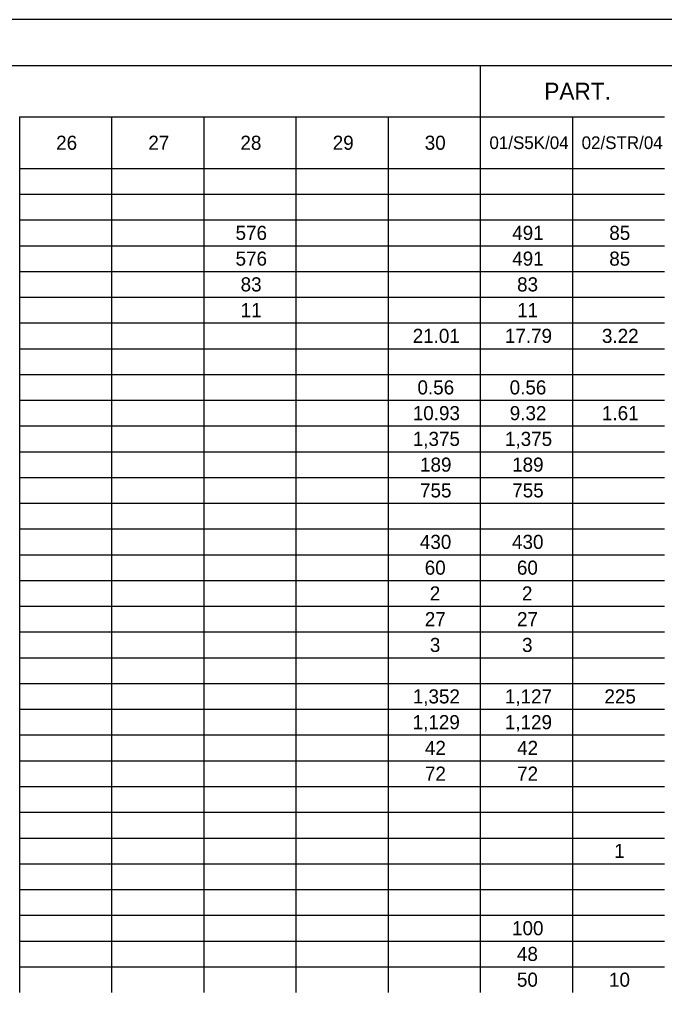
# Model space of a CAD drawing. Extents: x 0 to 34, y 0 to 22.
# Drawn here: x 8.52 to 15.54, y 11.42 to 22 of the extents above; entities that cross this region are included whole.
import ezdxf

# ---------------------------------------------------------------- set-up
doc = ezdxf.new("R2010")
doc.units = 0
for name, color, linetype in [('SH_Border', 7, 'Continuous'), ('SH_Cut_Line', 7, 'Continuous'), ('SH_Text', 7, 'Continuous')]:
    doc.layers.add(name, color=color, linetype=linetype)

msp = doc.modelspace()

# ---------------------------------------------------------------- linework, layer by layer
at = {"layer": 'SH_Border'}
msp.add_lwpolyline([(1.5, 21.5), (33.5, 21.5), (33.5, 0.5), (1.5, 0.5)], close=True, dxfattribs=at)
at = {"layer": 'SH_Cut_Line'}
msp.add_lwpolyline([(0, 0), (34, 0), (34, 22), (0, 22)], close=True, dxfattribs=at)
at = {"layer": 'SH_Text'}
for p, q in [((8.519, 21.5), (9.521, 21.5)), ((9.521, 21.5), (11.527, 21.5)), ((11.527, 21.5), (12.529, 21.5)), ((12.529, 21.5), (13.532, 21.5)), ((13.532, 21.5), (14.535, 21.5)), ((13.532, 21.5), (13.532, 21.22)), ((14.535, 21.5), (15.537, 21.5)), ((13.532, 21.22), (13.532, 20.94)), ((8.519, 20.94), (9.521, 20.94)), ((8.519, 20.94), (8.519, 20.66)), ((9.521, 20.94), (11.527, 20.94)), ((9.521, 20.94), (9.521, 20.66)), ((10.524, 20.94), (10.524, 20.66)), ((11.527, 20.94), (12.529, 20.94)), ((11.527, 20.94), (11.527, 20.66)), ((12.529, 20.94), (13.532, 20.94)), ((12.529, 20.94), (12.529, 20.66)), ((13.532, 20.94), (14.535, 20.94)), ((13.532, 20.94), (13.532, 20.66)), ((14.535, 20.94), (15.537, 20.94)), ((14.535, 20.94), (14.535, 20.66)), ((8.519, 20.66), (8.519, 20.38)), ((9.521, 20.66), (9.521, 20.38)), ((10.524, 20.66), (10.524, 20.38)), ((11.527, 20.66), (11.527, 20.38)), ((12.529, 20.66), (12.529, 20.38)), ((13.532, 20.66), (13.532, 20.38)), ((14.535, 20.66), (14.535, 20.38)), ((8.519, 20.38), (9.521, 20.38)), ((8.519, 20.38), (8.519, 20.1)), ((9.521, 20.38), (11.527, 20.38)), ((9.521, 20.38), (9.521, 20.1)), ((10.524, 20.38), (10.524, 20.1)), ((11.527, 20.38), (12.529, 20.38)), ((11.527, 20.38), (11.527, 20.1)), ((12.529, 20.38), (13.532, 20.38)), ((12.529, 20.38), (12.529, 20.1)), ((13.532, 20.38), (14.535, 20.38)), ((13.532, 20.38), (13.532, 20.1)), ((14.535, 20.38), (15.537, 20.38)), ((14.535, 20.38), (14.535, 20.1)), ((8.519, 20.1), (9.521, 20.1)), ((8.519, 20.1), (8.519, 18.7)), ((9.521, 20.1), (11.527, 20.1)), ((9.521, 20.1), (9.521, 18.7)), ((10.524, 20.1), (10.524, 18.7)), ((11.527, 20.1), (12.529, 20.1)), ((11.527, 20.1), (11.527, 18.7)), ((12.529, 20.1), (13.532, 20.1)), ((12.529, 20.1), (12.529, 18.7)), ((13.532, 20.1), (14.535, 20.1)), ((13.532, 20.1), (13.532, 18.7)), ((14.535, 20.1), (15.537, 20.1)), ((14.535, 20.1), (14.535, 18.7)), ((8.519, 19.82), (9.521, 19.82)), ((9.521, 19.82), (11.527, 19.82)), ((11.527, 19.82), (12.529, 19.82)), ((12.529, 19.82), (13.532, 19.82)), ((13.532, 19.82), (14.535, 19.82)), ((14.535, 19.82), (15.537, 19.82)), ((8.519, 19.54), (9.521, 19.54)), ((9.521, 19.54), (11.527, 19.54)), ((11.527, 19.54), (12.529, 19.54)), ((12.529, 19.54), (13.532, 19.54)), ((13.532, 19.54), (14.535, 19.54)), ((14.535, 19.54), (15.537, 19.54)), ((8.519, 19.26), (9.521, 19.26)), ((9.521, 19.26), (11.527, 19.26)), ((11.527, 19.26), (12.529, 19.26)), ((12.529, 19.26), (13.532, 19.26)), ((13.532, 19.26), (14.535, 19.26)), ((14.535, 19.26), (15.537, 19.26)), ((8.519, 18.98), (9.521, 18.98)), ((9.521, 18.98), (11.527, 18.98)), ((11.527, 18.98), (12.529, 18.98)), ((12.529, 18.98), (13.532, 18.98)), ((13.532, 18.98), (14.535, 18.98)), ((14.535, 18.98), (15.537, 18.98)), ((8.519, 18.7), (9.521, 18.7)), ((8.519, 18.7), (8.519, 18.14)), ((9.521, 18.7), (11.527, 18.7)), ((9.521, 18.7), (9.521, 18.14)), ((10.524, 18.7), (10.524, 18.14)), ((11.527, 18.7), (12.529, 18.7)), ((11.527, 18.7), (11.527, 18.14)), ((12.529, 18.7), (13.532, 18.7)), ((12.529, 18.7), (12.529, 18.14)), ((13.532, 18.7), (14.535, 18.7)), ((13.532, 18.7), (13.532, 18.14)), ((14.535, 18.7), (15.537, 18.7)), ((14.535, 18.7), (14.535, 18.14)), ((8.519, 18.42), (9.521, 18.42)), ((9.521, 18.42), (11.527, 18.42)), ((11.527, 18.42), (12.529, 18.42)), ((12.529, 18.42), (13.532, 18.42)), ((13.532, 18.42), (14.535, 18.42)), ((14.535, 18.42), (15.537, 18.42)), ((8.519, 18.14), (9.521, 18.14)), ((8.519, 18.14), (8.519, 17.86)), ((9.521, 18.14), (11.527, 18.14)), ((9.521, 18.14), (9.521, 17.86)), ((10.524, 18.14), (10.524, 17.86)), ((11.527, 18.14), (12.529, 18.14)), ((11.527, 18.14), (11.527, 17.86)), ((12.529, 18.14), (13.532, 18.14)), ((12.529, 18.14), (12.529, 17.86)), ((13.532, 18.14), (14.535, 18.14)), ((13.532, 18.14), (13.532, 17.86)), ((14.535, 18.14), (15.537, 18.14)), ((14.535, 18.14), (14.535, 17.86)), ((8.519, 17.86), (9.521, 17.86)), ((8.519, 17.86), (8.519, 17.58)), ((9.521, 17.86), (11.527, 17.86)), ((9.521, 17.86), (9.521, 17.58)), ((10.524, 17.86), (10.524, 17.58)), ((11.527, 17.86), (12.529, 17.86)), ((11.527, 17.86), (11.527, 17.58)), ((12.529, 17.86), (13.532, 17.86)), ((12.529, 17.86), (12.529, 17.58)), ((13.532, 17.86), (14.535, 17.86)), ((13.532, 17.86), (13.532, 17.58)), ((14.535, 17.86), (15.537, 17.86)), ((14.535, 17.86), (14.535, 17.58)), ((8.519, 17.58), (9.521, 17.58)), ((8.519, 17.58), (8.519, 17.3)), ((9.521, 17.58), (11.527, 17.58)), ((9.521, 17.58), (9.521, 17.3)), ((10.524, 17.58), (10.524, 17.3)), ((11.527, 17.58), (12.529, 17.58)), ((11.527, 17.58), (11.527, 17.3)), ((12.529, 17.58), (13.532, 17.58)), ((12.529, 17.58), (12.529, 17.3)), ((13.532, 17.58), (14.535, 17.58)), ((13.532, 17.58), (13.532, 17.3)), ((14.535, 17.58), (15.537, 17.58)), ((14.535, 17.58), (14.535, 17.3)), ((8.519, 17.3), (9.521, 17.3)), ((8.519, 17.3), (8.519, 17.02)), ((9.521, 17.3), (11.527, 17.3)), ((9.521, 17.3), (9.521, 17.02)), ((10.524, 17.3), (10.524, 17.02)), ((11.527, 17.3), (12.529, 17.3)), ((11.527, 17.3), (11.527, 17.02)), ((12.529, 17.3), (13.532, 17.3)), ((12.529, 17.3), (12.529, 17.02)), ((13.532, 17.3), (14.535, 17.3)), ((13.532, 17.3), (13.532, 17.02)), ((14.535, 17.3), (15.537, 17.3)), ((14.535, 17.3), (14.535, 17.02)), ((8.519, 17.02), (9.521, 17.02)), ((8.519, 17.02), (8.519, 16.74)), ((9.521, 17.02), (11.527, 17.02)), ((9.521, 17.02), (9.521, 16.74)), ((10.524, 17.02), (10.524, 16.74)), ((11.527, 17.02), (12.529, 17.02)), ((11.527, 17.02), (11.527, 16.74)), ((12.529, 17.02), (13.532, 17.02)), ((12.529, 17.02), (12.529, 16.74)), ((13.532, 17.02), (14.535, 17.02)), ((13.532, 17.02), (13.532, 16.74)), ((14.535, 17.02), (15.537, 17.02)), ((14.535, 17.02), (14.535, 16.74)), ((8.519, 16.74), (9.521, 16.74)), ((8.519, 16.74), (8.519, 16.18)), ((9.521, 16.74), (11.527, 16.74)), ((9.521, 16.74), (9.521, 16.18)), ((10.524, 16.74), (10.524, 16.18)), ((11.527, 16.74), (12.529, 16.74)), ((11.527, 16.74), (11.527, 16.18)), ((12.529, 16.74), (13.532, 16.74)), ((12.529, 16.74), (12.529, 16.18)), ((13.532, 16.74), (14.535, 16.74)), ((13.532, 16.74), (13.532, 16.18)), ((14.535, 16.74), (15.537, 16.74)), ((14.535, 16.74), (14.535, 16.18)), ((8.519, 16.46), (9.521, 16.46)), ((9.521, 16.46), (11.527, 16.46)), ((11.527, 16.46), (12.529, 16.46)), ((12.529, 16.46), (13.532, 16.46)), ((13.532, 16.46), (14.535, 16.46)), ((14.535, 16.46), (15.537, 16.46)), ((8.519, 16.18), (9.521, 16.18)), ((8.519, 16.18), (8.519, 15.9)), ((9.521, 16.18), (11.527, 16.18)), ((9.521, 16.18), (9.521, 15.9)), ((10.524, 16.18), (10.524, 15.9)), ((11.527, 16.18), (12.529, 16.18)), ((11.527, 16.18), (11.527, 15.9)), ((12.529, 16.18), (13.532, 16.18)), ((12.529, 16.18), (12.529, 15.9)), ((13.532, 16.18), (14.535, 16.18)), ((13.532, 16.18), (13.532, 15.9)), ((14.535, 16.18), (15.537, 16.18)), ((14.535, 16.18), (14.535, 15.9)), ((8.519, 15.9), (9.521, 15.9)), ((8.519, 15.9), (8.519, 15.62)), ((9.521, 15.9), (11.527, 15.9)), ((9.521, 15.9), (9.521, 15.62)), ((10.524, 15.9), (10.524, 15.62)), ((11.527, 15.9), (12.529, 15.9)), ((11.527, 15.9), (11.527, 15.62)), ((12.529, 15.9), (13.532, 15.9)), ((12.529, 15.9), (12.529, 15.62)), ((13.532, 15.9), (14.535, 15.9)), ((13.532, 15.9), (13.532, 15.62)), ((14.535, 15.9), (15.537, 15.9)), ((14.535, 15.9), (14.535, 15.62)), ((8.519, 15.62), (9.521, 15.62)), ((8.519, 15.62), (8.519, 15.34)), ((9.521, 15.62), (11.527, 15.62)), ((9.521, 15.62), (9.521, 15.34)), ((10.524, 15.62), (10.524, 15.34)), ((11.527, 15.62), (12.529, 15.62)), ((11.527, 15.62), (11.527, 15.34)), ((12.529, 15.62), (13.532, 15.62)), ((12.529, 15.62), (12.529, 15.34)), ((13.532, 15.62), (14.535, 15.62)), ((13.532, 15.62), (13.532, 15.34)), ((14.535, 15.62), (15.537, 15.62)), ((14.535, 15.62), (14.535, 15.34)), ((8.519, 15.34), (9.521, 15.34)), ((8.519, 15.34), (8.519, 14.78)), ((9.521, 15.34), (11.527, 15.34)), ((9.521, 15.34), (9.521, 14.78)), ((10.524, 15.34), (10.524, 14.78)), ((11.527, 15.34), (12.529, 15.34)), ((11.527, 15.34), (11.527, 14.78)), ((12.529, 15.34), (13.532, 15.34)), ((12.529, 15.34), (12.529, 14.78)), ((13.532, 15.34), (14.535, 15.34)), ((13.532, 15.34), (13.532, 14.78)), ((14.535, 15.34), (15.537, 15.34)), ((14.535, 15.34), (14.535, 14.78)), ((8.519, 15.06), (9.521, 15.06)), ((9.521, 15.06), (11.527, 15.06)), ((11.527, 15.06), (12.529, 15.06)), ((12.529, 15.06), (13.532, 15.06)), ((13.532, 15.06), (14.535, 15.06)), ((14.535, 15.06), (15.537, 15.06)), ((8.519, 14.78), (9.521, 14.78)), ((8.519, 14.78), (8.519, 14.5)), ((9.521, 14.78), (11.527, 14.78)), ((9.521, 14.78), (9.521, 14.5)), ((10.524, 14.78), (10.524, 14.5)), ((11.527, 14.78), (12.529, 14.78)), ((11.527, 14.78), (11.527, 14.5)), ((12.529, 14.78), (13.532, 14.78)), ((12.529, 14.78), (12.529, 14.5)), ((13.532, 14.78), (14.535, 14.78)), ((13.532, 14.78), (13.532, 14.5)), ((14.535, 14.78), (15.537, 14.78)), ((14.535, 14.78), (14.535, 14.5)), ((8.519, 14.5), (9.521, 14.5)), ((8.519, 14.5), (8.519, 14.22)), ((9.521, 14.5), (11.527, 14.5)), ((9.521, 14.5), (9.521, 14.22)), ((10.524, 14.5), (10.524, 14.22)), ((11.527, 14.5), (12.529, 14.5)), ((11.527, 14.5), (11.527, 14.22)), ((12.529, 14.5), (13.532, 14.5)), ((12.529, 14.5), (12.529, 14.22)), ((13.532, 14.5), (14.535, 14.5)), ((13.532, 14.5), (13.532, 14.22)), ((14.535, 14.5), (15.537, 14.5)), ((14.535, 14.5), (14.535, 14.22)), ((8.519, 14.22), (9.521, 14.22)), ((8.519, 14.22), (8.519, 13.94)), ((9.521, 14.22), (11.527, 14.22)), ((9.521, 14.22), (9.521, 13.94)), ((10.524, 14.22), (10.524, 13.94)), ((11.527, 14.22), (12.529, 14.22)), ((11.527, 14.22), (11.527, 13.94)), ((12.529, 14.22), (13.532, 14.22)), ((12.529, 14.22), (12.529, 13.94)), ((13.532, 14.22), (14.535, 14.22)), ((13.532, 14.22), (13.532, 13.94)), ((14.535, 14.22), (15.537, 14.22)), ((14.535, 14.22), (14.535, 13.94)), ((8.519, 13.94), (9.521, 13.94)), ((8.519, 13.94), (8.519, 11.7)), ((9.521, 13.94), (11.527, 13.94)), ((9.521, 13.94), (9.521, 11.7)), ((10.524, 13.94), (10.524, 11.7)), ((11.527, 13.94), (12.529, 13.94)), ((11.527, 13.94), (11.527, 11.7)), ((12.529, 13.94), (13.532, 13.94)), ((12.529, 13.94), (12.529, 11.7)), ((13.532, 13.94), (14.535, 13.94)), ((13.532, 13.94), (13.532, 11.7)), ((14.535, 13.94), (15.537, 13.94)), ((14.535, 13.94), (14.535, 11.7)), ((8.519, 13.66), (9.521, 13.66)), ((9.521, 13.66), (11.527, 13.66)), ((11.527, 13.66), (12.529, 13.66)), ((12.529, 13.66), (13.532, 13.66)), ((13.532, 13.66), (14.535, 13.66)), ((14.535, 13.66), (15.537, 13.66)), ((8.519, 13.38), (9.521, 13.38)), ((9.521, 13.38), (11.527, 13.38)), ((11.527, 13.38), (12.529, 13.38)), ((12.529, 13.38), (13.532, 13.38)), ((13.532, 13.38), (14.535, 13.38)), ((14.535, 13.38), (15.537, 13.38)), ((8.519, 13.1), (9.521, 13.1)), ((9.521, 13.1), (11.527, 13.1)), ((11.527, 13.1), (12.529, 13.1)), ((12.529, 13.1), (13.532, 13.1)), ((13.532, 13.1), (14.535, 13.1)), ((14.535, 13.1), (15.537, 13.1)), ((8.519, 12.82), (9.521, 12.82)), ((9.521, 12.82), (11.527, 12.82)), ((11.527, 12.82), (12.529, 12.82)), ((12.529, 12.82), (13.532, 12.82)), ((13.532, 12.82), (14.535, 12.82)), ((14.535, 12.82), (15.537, 12.82)), ((8.519, 12.54), (9.521, 12.54)), ((9.521, 12.54), (11.527, 12.54)), ((11.527, 12.54), (12.529, 12.54)), ((12.529, 12.54), (13.532, 12.54)), ((13.532, 12.54), (14.535, 12.54)), ((14.535, 12.54), (15.537, 12.54)), ((8.519, 12.26), (9.521, 12.26)), ((9.521, 12.26), (11.527, 12.26)), ((11.527, 12.26), (12.529, 12.26)), ((12.529, 12.26), (13.532, 12.26)), ((13.532, 12.26), (14.535, 12.26)), ((14.535, 12.26), (15.537, 12.26)), ((8.519, 11.98), (9.521, 11.98)), ((9.521, 11.98), (11.527, 11.98)), ((11.527, 11.98), (12.529, 11.98)), ((12.529, 11.98), (13.532, 11.98)), ((13.532, 11.98), (14.535, 11.98)), ((14.535, 11.98), (15.537, 11.98)), ((8.519, 11.7), (9.521, 11.7)), ((8.519, 11.7), (8.519, 11.42)), ((9.521, 11.7), (11.527, 11.7)), ((9.521, 11.7), (9.521, 11.42)), ((10.524, 11.7), (10.524, 11.42)), ((11.527, 11.7), (12.529, 11.7)), ((11.527, 11.7), (11.527, 11.42)), ((12.529, 11.7), (13.532, 11.7)), ((12.529, 11.7), (12.529, 11.42)), ((13.532, 11.7), (14.535, 11.7)), ((13.532, 11.7), (13.532, 11.42)), ((14.535, 11.7), (15.537, 11.7)), ((14.535, 11.7), (14.535, 11.42))]:
    msp.add_line(p, q, dxfattribs=at)

# ---------------------------------------------------------------- texts
for s, height, p in [('PART.', 0.184, (14.229, 21.128)), ('26', 0.1533, (8.918, 20.583)), ('27', 0.1533, (9.921, 20.583)), ('28', 0.1533, (10.923, 20.583)), ('29', 0.1533, (11.927, 20.583)), ('30', 0.1533, (12.928, 20.583)), ('01/S5K/04', 0.138, (13.632, 20.591)), ('02/STR/04', 0.138, (14.635, 20.591)), ('576', 0.1533, (10.87, 19.603)), ('491', 0.1533, (13.88, 19.603)), ('85', 0.1533, (14.936, 19.603)), ('576', 0.1533, (10.87, 19.323)), ('491', 0.1533, (13.88, 19.323)), ('85', 0.1533, (14.936, 19.323)), ('83', 0.1533, (10.925, 19.043)), ('83', 0.1533, (13.933, 19.043)), ('11', 0.1533, (10.925, 18.763)), ('11', 0.1533, (13.933, 18.763)), ('21.01', 0.1533, (12.797, 18.483)), ('17.79', 0.1533, (13.8, 18.483)), ('3.22', 0.1533, (14.856, 18.483)), ('0.56', 0.1533, (12.849, 17.923)), ('0.56', 0.1533, (13.852, 17.923)), ('10.93', 0.1533, (12.798, 17.643)), ('9.32', 0.1533, (13.853, 17.643)), ('1.61', 0.1533, (14.856, 17.643)), ('1,375', 0.1533, (12.798, 17.363)), ('1,375', 0.1533, (13.801, 17.363)), ('189', 0.1533, (12.877, 17.083)), ('189', 0.1533, (13.879, 17.083)), ('755', 0.1533, (12.877, 16.803)), ('755', 0.1533, (13.88, 16.803)), ('430', 0.1533, (12.875, 16.243)), ('430', 0.1533, (13.878, 16.243)), ('60', 0.1533, (12.928, 15.963)), ('60', 0.1533, (13.931, 15.963)), ('2', 0.153, (12.983, 15.683)), ('2', 0.153, (13.986, 15.683)), ('27', 0.1533, (12.929, 15.403)), ('27', 0.1533, (13.932, 15.403)), ('3', 0.153, (12.984, 15.123)), ('3', 0.153, (13.987, 15.123)), ('1,352', 0.1533, (12.798, 14.563)), ('1,127', 0.1533, (13.8, 14.563)), ('225', 0.1533, (14.883, 14.563)), ('1,129', 0.1533, (12.797, 14.283)), ('1,129', 0.1533, (13.8, 14.283)), ('42', 0.1533, (12.93, 14.003)), ('42', 0.1533, (13.933, 14.003)), ('72', 0.1533, (12.93, 13.723)), ('72', 0.1533, (13.933, 13.723)), ('1', 0.153, (14.989, 12.883)), ('100', 0.1533, (13.878, 12.043)), ('48', 0.1533, (13.931, 11.763)), ('50', 0.1533, (13.931, 11.483)), ('10', 0.1533, (14.933, 11.483))]:
    msp.add_text(s, height=height, dxfattribs=at).set_placement(p)

doc.saveas('drawing.dxf')
